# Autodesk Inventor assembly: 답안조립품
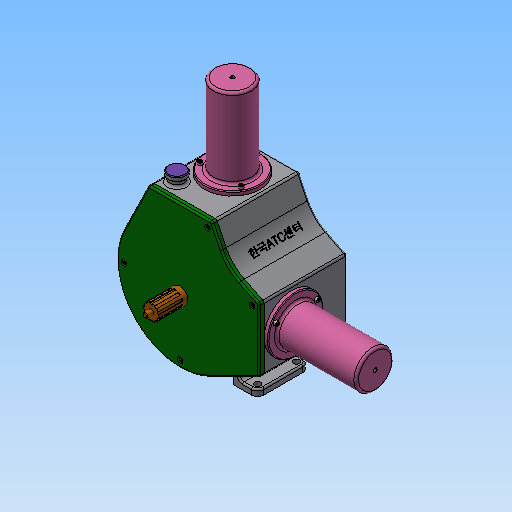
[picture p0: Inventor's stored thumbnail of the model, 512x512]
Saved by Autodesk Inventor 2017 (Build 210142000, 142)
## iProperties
Part Number: 답안조립품
Material: 일반
Document SubType Name: Assembly
Designer: MRC
Mass: 2899.53 g
Surface Area: 4101.78 cm^2
Volume: 1119.43 cm^3
Density: 2.59018 g/cm^3
Author: MRC
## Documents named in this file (13)
- C:\Users\MRC\Desktop\611109V1002\답안조립품.iam
- C:\Users\MRC\Desktop\611109V1002\본체.ipt
- C:\Users\MRC\Desktop\611109V1002\너트 M3.ipt
- C:\Users\MRC\Desktop\611109V1002\베어링 20 x 37 x 9.ipt
- C:\Users\MRC\Desktop\611109V1002\볼트 M3 x 12.ipt
- C:\Users\MRC\Desktop\611109V1002\실린더.ipt
- C:\Users\MRC\Desktop\611109V1002\앞커버.ipt
- C:\Users\MRC\Desktop\611109V1002\축.ipt
- C:\Users\MRC\Desktop\611109V1002\측정게이지.ipt
- C:\Users\MRC\Desktop\611109V1002\커넥팅로드 캡.ipt
- C:\Users\MRC\Desktop\611109V1002\커넥팅로드.ipt
- C:\Users\MRC\Desktop\611109V1002\피스톤 핀.ipt
- C:\Users\MRC\Desktop\611109V1002\피스톤.ipt
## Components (4 placed, 2 different names)
1. 피스톤 핀:1
2. 피스톤:1
3. 피스톤:2
4. 피스톤 핀:2
